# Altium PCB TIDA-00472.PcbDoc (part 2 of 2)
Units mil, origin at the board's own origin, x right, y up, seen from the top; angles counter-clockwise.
Board outline 3661.41 x 4133.85 mil, 2 copper layers (Top Layer, Bottom Layer), stack 62 mil thick; 187 components, 96 nets, 460 pads, 195 vias.
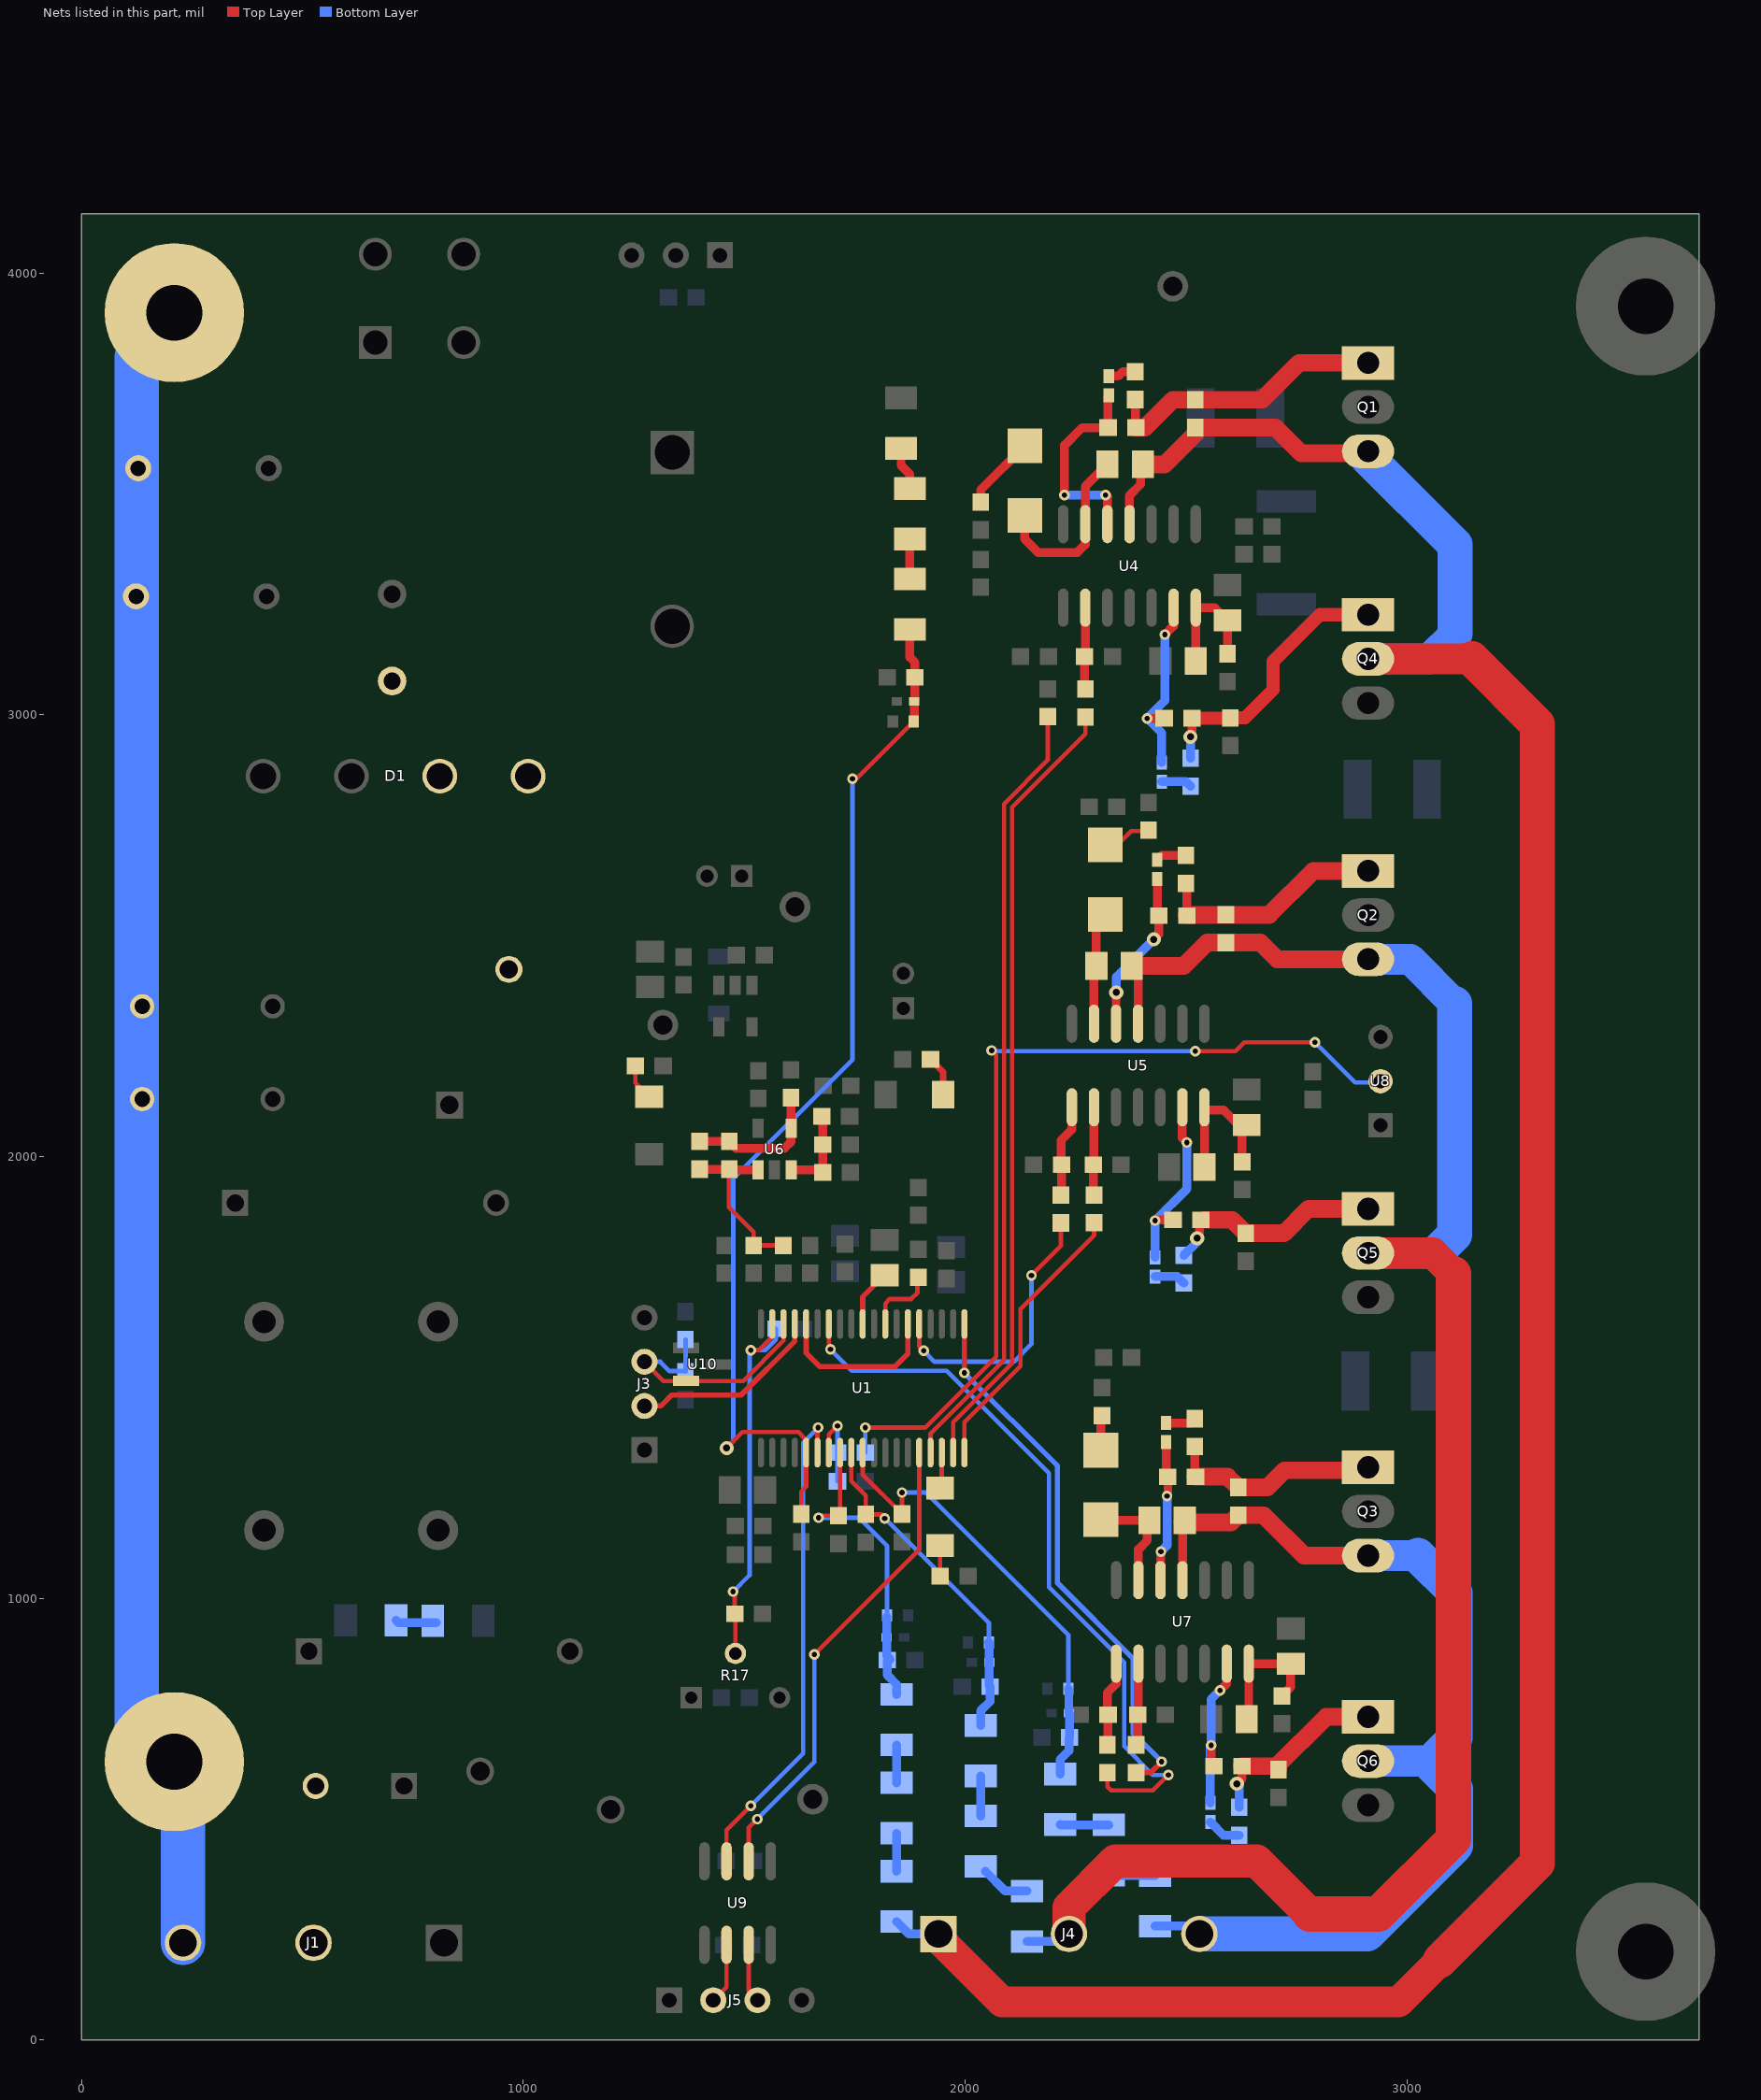
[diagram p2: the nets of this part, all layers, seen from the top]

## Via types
v1: diameter 32, hole 16, Top Layer to Bottom Layer, tented both sides, 154 vias
v2: diameter 24, hole 12, Top Layer to Bottom Layer, tented both sides, 39 vias
v3: diameter 28, hole 14, Top Layer to Bottom Layer, tented bottom, 2 vias

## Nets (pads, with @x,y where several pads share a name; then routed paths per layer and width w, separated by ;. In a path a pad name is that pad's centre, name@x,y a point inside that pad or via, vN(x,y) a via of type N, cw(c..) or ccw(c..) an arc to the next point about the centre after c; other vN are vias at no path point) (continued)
NetC28_1: C28.1 D3.1 U4.13 | length 405.7
  Top Layer w20: D3.1@2135,3451.26 2135,3397.5 2165,3367.5 2254,3367.5 2272,3385.5 U4.13@2272,3431.43 2272,3516.94 C28.1@2317,3561.94
NetC29_1: C29.1 R33.2 U4.2 | length 185.7
  Top Layer w20: R33.2@2272,3058 2270.5,3059.5 C29.1@2270.5,3131.94 2272,3133.43 U4.2@2272,3242.45
NetC30_2: C30.2 C31.1 R36.2 U4.7 | length 280
  Top Layer w20: C30.2@2522,3121.94 U4.7@2522,3242.45 2565.06,3242.45 C31.1@2594,3213.5 R36.2@2594,3138
NetC32_1: C32.1 R42.2 U5.1 | length 210.3
  Top Layer w20: R42.2@2216.57,1912.57 2218.06,1914.06 C32.1@2218.06,1981.07 2217,1982.13 2217,2036.5 2241.57,2061.07 U5.1@2241.57,2111.58
NetC34_1: C34.1 D4.1 U5.13 | length 270.8
  Top Layer w20: U5.13@2291.57,2300.56 2291.57,2415.07 C34.1@2297,2420.5 ; C34.1@2297,2431.5 D4.1@2297,2514.76 ; D4.1@2314,2531.76 D4.1@2297,2514.76 ; D4.1@2317,2547.76 2297,2527.76 D4.1@2297,2514.76
NetC35_1: C35.1 R45.2 U5.2 | length 200
  Top Layer w20: U5.2@2291.57,2111.58 2291.57,1982.57 C35.1@2290.07,1981.07 2290.07,1914.93 R45.2@2292,1913
NetC36_1: C36.1 R47.1 R52.1 R57.1 U6.1 | length 396.4
  Top Layer w10: R47.1@1466.08,1971.26 1465,1970.19 1465,1885 1521.08,1828.92 R52.1@1521.08,1798.76 R57.1@1588.28,1798.76
  Top Layer w20: C36.1@1399.08,1971.26 R47.1@1466.08,1971.26 1468.07,1969.27 U6.1@1531.27,1969.27
NetC36_2: C36.2 R47.2 R49.2 U6.4 | length 319.1
  Top Layer w20: C36.2@1399.08,2034.26 R47.2@1466.08,2034.26 1481.57,2018.76 1591.08,2018.76 1606.08,2033.76 U6.4@1606.08,2063.76 R49.2@1606.08,2133.26
NetC37_2: C37.2 C38.1 R50.2 U5.7 | length 335.2
  Top Layer w20: C37.2@2541.57,1976.07 U5.7@2541.57,2111.58 2548.15,2105 2585,2105 2618.5,2071.5 C38.1@2637,2071.5 2627,2061.5 R50.2@2627,1988
NetC40_1: C40.1 R54.2 R58.2 U6.3 | length 201.6
  Top Layer w20: U6.3@1606.08,1969.27 1672.07,1969.27 C40.1@1677.58,1963.76 R58.2@1677.58,2026.76 1677.58,2088.76 R54.2@1675.58,2090.76
NetC41_1: C41.1 R56.2 U7.1 | length 193.5
  Top Layer w20: R56.2@2322,668 2323.5,669.5 C41.1@2323.5,736.5 2322,738 2322,786.5 2342,806.5 U7.1@2342,852.02
NetC43_1: C43.1 D5.1 U7.13 | length 256.4
  Top Layer w20: D5.1@2307,1177.76 2308.26,1176.5 C43.1@2417,1176.5 2412,1171.5 2412,1130.5 2392,1110.5 U7.13@2392,1040.99
NetC44_1: C44.1 R59.2 U7.2 | length 186.1
  Top Layer w20: R59.2@2387,668 2390.5,671.5 C44.1@2390.5,736.5 2392,738 U7.2@2392,852.02
NetC45_2: C45.2 C46.1 R62.2 U7.7 | length 303.6
  Top Layer w20: C45.2@2637,726.5 2642,731.5 U7.7@2642,852.02 2736.49,852.02 C46.1@2737,851.5 2737,799 R62.2@2717,779
NetC54_1: C54.1 U1.29 | length 131.6
  Top Layer w12: U1.29@1768.08,1620.93 1768.08,1682.26 1817.08,1731.26 C54.1@1818.08,1731.26
NetD1_1: D1.1 L1.1
NetD1_2: D1.2 RT1.2
NetD2_1: D2.1 R7.2 | length 69.5
  Top Layer w10: D2.1@1943.08,1119.3 1943.08,1050.43 R7.2@1943.5,1050
NetD2_2: D2.2 U1.17 | length 106.1
  Top Layer w10: D2.2@1938.12,1227.26 1938.12,1249.22 1947.21,1258.32 U1.17@1947.21,1329.59
NetD3_2: D3.2 R31.2 | length 168.7
  Top Layer w20: R31.2@2035,3481.5 2035,3508.74 D3.2@2135,3608.74
NetD4_2: D4.2 R41.2 | length 112.2
  Top Layer w10: D4.2@2317,2705.24 2344.24,2705.24 2375.5,2736.5 2412,2736.5 R41.2@2415,2733.5
NetD5_2: D5.2 R55.2 | length 79.5
  Top Layer w20: D5.2@2307,1335.24 2307,1410.5 R55.2@2310,1413.5
NetD6_1: D6.1 R66.2 | length 91.8
  Top Layer w15: R66.2@1921.5,2220 1949.96,2191.54 D6.1@1949.96,2140
NetD7_1: D7.1 R67.2 | length 83.1
  Top Layer w10: R67.2@1253.5,2205 1253.5,2166.46 D7.1@1285,2134.96
NetD13_1: D13.1 R34.1 U4.12 | length 467.9
  Top Layer w20: v2(2225,3497.5) 2225,3610 2265,3650 R34.1@2323.5,3650 2323.5,3721.85 D13.1@2325,3723.35 ; v2(2318,3497.5) 2322,3493.5 U4.12@2322,3431.43
  Bottom Layer w20: v2(2225,3497.5) v2(2318,3497.5) v2@2322,3493.5
NetD13_2: D13.2 R2.1 | length 64.1
  Top Layer w20: D13.2@2325,3766.65 2346.65,3766.65 2356.5,3776.5 R2.1@2385,3776.5
NetD14_1: D14.1 R37.1 U4.6 | length 419.4
  Top Layer w20: v2(2411.94,2991.94) R37.1@2442,2991.94 ; v2(2452,3181.5) 2472,3201.5 U4.6@2472,3242.45
  Bottom Layer w20: D14.1@2445,2891.65 2445,2958.87 v2(2411.94,2991.94) 2452,3032 v2(2452,3181.5)
NetD14_2: D14.2 R3.1 | length 69.1
  Bottom Layer w20: D14.2@2445,2848.35 2500.16,2848.35 R3.1@2510,2838.5
NetD15_1: D15.1 R46.1 U5.12 | length 352.1
  Top Layer w20: U5.12@2341.57,2300.56 2341.57,2361.07 v1@2342,2361.5 ; v1(2427,2491.5) 2438.5,2503.01 R46.1@2438.5,2545 ; D15.1@2435,2628.35 2435,2553.01 R46.1@2436.5,2551.5
  Bottom Layer w20: v1(2342,2371.5) 2342,2406.5 v1(2427,2491.5)
NetD15_2: D15.2 R6.1 | length 69.1
  Top Layer w20: D15.2@2435,2671.65 2444.84,2681.5 R6.1@2500,2681.5
NetD16_1: D16.1 R51.1 U5.6 | length 406.7
  Top Layer w20: v2(2430,1855) 2431.5,1856.5 R51.1@2462,1856.5 ; U5.6@2491.57,2111.58 2491.57,2041.94 v2(2502,2031.5)
  Bottom Layer w20: D16.1@2430,1771.65 v2(2430,1855) 2502,1927 v2(2502,2031.5)
NetD16_2: D16.2 R24.1 | length 71.1
  Bottom Layer w20: D16.2@2430,1728.35 2480.16,1728.35 R24.1@2495,1713.5
NetD17_1: D17.1 R60.1 U7.12 | length 320.8
  Top Layer w20: U7.12@2442,1040.99 2443,1041.99 v2(2443,1105.5) ; D17.1@2455,1353.35 2455,1278.5 R60.1@2458.5,1275 ; v2(2457,1231.5) 2459,1233.5 R60.1@2459,1275
  Bottom Layer w20: v2(2443,1105.5) 2457,1119.5 v2(2457,1231.5)
NetD17_2: D17.2 R25.1 | length 69.1
  Top Layer w20: D17.2@2455,1396.65 2510.16,1396.65 R25.1@2520,1406.5
NetD18_1: D18.1 R63.1 U7.6 | length 377.7
  Top Layer w20: R63.1@2557,620 v2(2557,667) ; v2(2577,791.5) 2592,806.5 U7.6@2592,852.02
  Bottom Layer w20: D18.1@2555,536.65 2555,665 v2(2557,667) 2557,771.5 v2(2577,791.5)
NetD18_2: D18.2 R26.1 | length 77.4
  Bottom Layer w20: D18.2@2555,493.35 2584.84,463.5 R26.1@2620,463.5
NetF1_2: F1.2 J1.2
NetR1_1: R1.1 R4.2 | length 92.9
  Bottom Layer w20: R1.1@712.09,950 717.09,945 R4.2@802.91,945
NetR8_1: R8.1 R13.2 | length 99.1
  Top Layer w20: R8.1@1855,3602.91 1855,3564.49 1875,3544.49 R13.2@1875,3512.09
NetR9_1: R9.1 R14.2 | length 85.8
  Bottom Layer w20: R9.1@1845,382.09 R14.2@1845,467.91
NetR10_1: R10.1 R15.2 | length 112.8
  Bottom Layer w20: R15.2@2045.83,382.09 2090.83,337.09 R10.1@2140,337.09
NetR11_1: R11.1 R16.2 | length 105.3
  Bottom Layer w20: R16.2@2325,372.91 2325.83,372.09 R11.1@2430,372.09
NetR13_1: R13.1 R18.2 | length 90.8
  Top Layer w20: R18.2@1875,3307.09 R13.1@1875,3397.91
NetR14_1: R14.1 R19.2 | length 85.8
  Bottom Layer w20: R14.1@1845,582.09 R19.2@1845,667.91
NetR15_1: R15.1 R20.2 | length 90.8
  Bottom Layer w20: R15.1@2035,507.09 R20.2@2035,597.91
NetR16_1: R16.1 R21.2 | length 110.3
  Bottom Layer w20: R21.2@2215,487.91 2215.83,487.09 R16.1@2325,487.09
NetR65_2: R65.2 U8.2 | length 2046
  Top Layer w10: v2(1774.08,1386.26) 1909.43,1386.26 2070,1546.83 2070,2230 v2(2060,2240) ; v2(2521,2238.5) 2612,2238.5 2632,2258.5 v2(2792,2258.5)
  Bottom Layer w10: R65.2@1773.98,1329.59 1773.98,1386.17 v2(1774.08,1386.26) ; v2(2060,2240) 2061.5,2238.5 v2(2521,2238.5) ; v2(2792,2258.5) 2883,2167.5 2940,2167.5 U8.2@2940,2170.5
NetR68_2: R68.2 U1.27 | length 165.5
  Top Layer w10: U1.27@1819.26,1620.93 1819.26,1667.45 1829.08,1677.26 1878.08,1677.26 1892.08,1691.26 1892.08,1724.77 R68.2@1894.08,1726.77
OC_FLT: U1.25 U1.34 | length 388.3
  Top Layer w12: U1.34@1640.12,1620.93 1640.12,1555.22 1671.08,1524.26 1841.08,1524.26 1870.44,1553.63 U1.25@1870.44,1620.93
PE: C1.1 C5.2 C6.2 C7.1 H1.1 H3.1 J1.3 | length 3774.8
  Bottom Layer w100: H3.1@225,3910 125,3810 125,715 H1.1@210,630 229.72,610.28 J1.3@229.72,220
PHU: C28.2 J4.1 Q1.3 Q4.2 R9.2 R35.1 U4.11 | length 6108.5
  Top Layer w20: U4.11@2372,3431.43 2372,3496.5 2397,3521.5 C28.2@2397,3561.94
  Top Layer w40: C28.2@2402,3566.94 2451.94,3566.94 2521,3636 R35.1@2521,3650.01 2702.5,3650.01 2761,3591.5 2907,3591.5 Q1.3@2912,3596.5
  Top Layer w70: J4.1@1939.72,230 2083.72,86 2981,86 3075,180 ; Q4.2@2912,3126.5 3147,3126.5
  Top Layer w80: 3075,180 3295,400 3295,2978.5 3147,3126.5
  Bottom Layer w20: R9.2@1845,267.91 1872.91,240 J4.1@1939.72,240
  Bottom Layer w70: Q4.2@2912,3126.5 3051,3126.5 3109,3184.5 ; Q1.3@2912,3581.5 Q1.3@2912,3596.5
  Bottom Layer w80: Q1.3@2912,3581.5 3109,3384.5 3109,3184.5
PHU_FB: C21.1 D9.2 R19.1 R28.2 U1.8 U11.1 | length 716.2
  Top Layer w10: v2(1668.08,1182.26) 1672.57,1186.76 C21.1@1713.08,1186.76 1716.9,1190.58 U1.8@1716.9,1329.59
  Bottom Layer w10: v2(1668.08,1182.26) 1759.5,1182.26 1823.38,1118.39 D9.2@1823.38,961.5
  Bottom Layer w20: D9.2@1822.32,957.57 U11.1@1822.32,911.5 1822.32,869.69 R28.2@1830.5,861.5 ; R28.2@1823.5,860 1823.5,826.5 1845,805 R19.1@1845,782.09
PHV: C34.2 J4.2 Q2.3 Q5.2 R10.2 R48.1 U5.11 | length 4359.4
  Top Layer w20: C34.2@2377,2420.5 2391.57,2405.94 U5.11@2391.57,2300.56
  Top Layer w40: C34.2@2377,2431.5 2495,2431.5 2547.5,2484.01 R48.1@2590,2484.01 2668.5,2484.01 2706,2446.5 Q2.3@2912,2446.5
  Top Layer w70: Q5.2@2912,1781.5 3058.5,1781.5 3105,1735
  Top Layer w75: J4.2@2235,240 2235,300 2340,405 2660,405 2780,285
  Top Layer w80: 2780,285 2935,285 3105,455 3105,1735
  Bottom Layer w20: R10.2@2140,222.91 2217.91,222.91 J4.2@2235,240
  Bottom Layer w70: Q5.2@2912,1781.5 3066,1781.5 ; Q2.3@2912,2446.5 3007,2446.5 3108,2345.5
  Bottom Layer w80: 3066,1781.5 3108,1823.5 3108,2345.5
PHV_FB: C22.1 D11.2 R20.1 R29.2 U1.9 U13.1 | length 766.4
  Top Layer w10: U1.9@1742.49,1329.59 1742.49,1264.85 1775.08,1232.26 C22.1@1775.08,1189.76 1810.58,1189.76 1811.08,1189.26 v2@1812.08,1189.26
  Bottom Layer w10: v2(1818.08,1180.26) 2053.62,944.72 D11.2@2053.62,900
  Bottom Layer w20: R20.1@2035,712.09 2035,745 2056.5,766.5 R29.2@2056.5,800 2054.68,801.81 U13.1@2054.68,855 2054.68,898.94 D11.2@2053.62,900
PHW: C43.2 J4.3 Q3.3 Q6.2 R11.2 R61.1 U7.11 | length 2355.2
  Top Layer w20: U7.11@2492,1040.99 C43.2@2492,1171.5
  Top Layer w40: C43.2@2492,1171.5 2601.5,1171.5 R61.1@2618,1188.01 2675.5,1188.01 2767,1096.5 Q3.3@2912,1096.5
  Bottom Layer w20: R11.2@2430,257.91 2512.36,257.91 J4.3@2530.28,240
  Bottom Layer w70: Q6.2@2912,631.5 3056,631.5 ; Q3.3@2912,1096.5 3025,1096.5
  Bottom Layer w80: J4.3@2530.28,240 2910,240 3110,440 3110,567.5 3051,626.5 ; 3025,1096.5 3109,1012.5 3109,684.5 3056,631.5
PHW_FB: C23.1 D10.2 R21.1 R30.2 U1.10 U12.1 | length 1059.5
  Top Layer w10: U1.10@1768.08,1329.59 1768.08,1279.76 C23.1@1857.08,1190.76 v2(1857.08,1239.26)
  Bottom Layer w10: v2(1857.08,1239.26) 1911.75,1239.26 2233.62,917.39 D10.2@2233.62,795
  Bottom Layer w20: R21.1@2215,602.09 2215,635 2235,655 2235,683.5 R30.2@2236.5,685 2236.5,738.19 U12.1@2234.68,740 2234.68,793.94 D10.2@2233.62,795
PWM_U_BOT: R33.1 U1.18 | length 1789.3
  Top Layer w10: U1.18@1972.8,1329.59 1972.8,1398.72 2106,1531.92 2106,2791.05 2272,2957.05 R33.1@2272,2995.01
PWM_U_TOP: R32.1 U1.16 | length 1775.8
  Top Layer w10: U1.16@1921.62,1329.59 1921.62,1373 2088,1539.38 2088,2798.5 2187,2897.5 R32.1@2187,2995.44
PWM_V_BOT: R45.1 U1.19 | length 642
  Top Layer w10: U1.19@1998.39,1329.59 1998.39,1398.86 2125,1525.46 2125,1655 2292,1822 R45.1@2292,1850.01
PWM_V_TOP: R42.1 U1.24 | length 642.1
  Top Layer w10: U1.24@1896.03,1620.93 1896.03,1570.31 v2(1906.08,1560.26) ; v2(2150,1730.5) 2216.57,1797.07 R42.1@2216.57,1849.57 R42.1@2213.5,1846.5
  Bottom Layer w10: v2(1906.08,1560.26) 1931.08,1535.26 2110.26,1535.26 2150,1575 v2(2150,1730.5)
PWM_W_BOT: R59.1 U1.20 | length 1244.5
  Top Layer w12: v2(1998.08,1510.26) 1998.08,1620.62 U1.20@1998.39,1620.93 ; R59.1@2387,605.01 2420.01,605.01 v2(2445,630)
  Bottom Layer w12: v2(1998.08,1510.26) 2209,1299.34 2209,1034.5 2380,863.5 2380,695 v2(2445,630)
PWM_W_TOP: R56.1 U1.32 | length 1673.4
  Top Layer w10: U1.32@1691.3,1620.93 1691.3,1567.04 v2(1695.08,1563.26) ; R56.1@2322,605.01 2322,573 2330,565 2425,565 v2(2460,600)
  Bottom Layer w10: v2(1695.08,1563.26) 1743.34,1515 1957.99,1515 2190,1282.99 2190,1025 2360,855 2360,665.02 2425.02,600 v2(2460,600)
RST: C57.1 J3.3 R12.1 U1.36 U10.2 | length 583.8
  Top Layer w10: J3.3@1274.08,1535.26 1317.48,1491.86 U10.2@1368.68,1491.86 1497.68,1491.86 1588.94,1583.13 U1.36@1588.94,1620.93
  Bottom Layer w10: J3.3@1274.08,1535.26 1310.08,1535.26 1331.08,1514.26 1365.57,1514.26 R12.1@1367.08,1512.76 C57.1@1367.08,1585.77
RX_IN: J5.3 U9.7 | length 133.8
  Top Layer w10: U9.7@1510,215.51 1510,110 J5.3@1530,90
SPEED_REF: C15.1 R17.2 R22.2 U1.37 | length 886.3
  Top Layer w10: v2(1475,1015) 1478.5,1011.5 R22.2@1478.5,965 1480,963.5 R17.2@1480,875 ; v2(1515.08,1561.26) 1532.8,1561.26 1563.35,1591.82 U1.37@1563.35,1620.93
  Bottom Layer w10: v2(1475,1015) 1512.08,1052.08 1512.08,1558.26 v2(1515.08,1561.26) 1547.34,1561.26 1571.58,1585.5 C15.1@1571.58,1610.26
TEMP_SENSE: C53.1 R65.1 U1.7 | length 194.1
  Top Layer w10: U1.7@1691.3,1329.59 1691.3,1370.49 v2(1710.99,1390.18)
  Bottom Layer w10: C53.1@1710.99,1264.85 R65.1@1710.99,1329.59 v2(1710.99,1390.18)
TEST: J3.2 U1.35 | length 440.3
  Top Layer w12: J3.2@1274.08,1435.26 1310.92,1435.26 1335.66,1460 1492.81,1460 1614.53,1581.72 U1.35@1614.53,1620.93
TX_OUT: J5.2 U9.6 | length 137.9
  Top Layer w10: J5.2@1430,90 1460,120 U9.6@1460,215.51
U_BOT: Q4.1 R3.2 R37.2 R38.2 | length 616.5
  Top Layer w20: v1(2510,2950) 2513.5,2953.5 R37.2@2513.5,2991.94
  Top Layer w30: R37.2@2522,2991.94 2598.94,2991.94 R38.2@2600,2993 2633.5,2993 2697,3056.5 2697,3120.5 2803,3226.5 Q4.1@2912,3226.5
  Bottom Layer w20: R3.2@2510,2901.5 v1(2510,2950)
U_TOP: Q1.1 R2.2 R34.2 R35.2 | length 650.3
  Top Layer w20: R2.2@2385,3713.5 2385,3651.5 R34.2@2386.5,3650
  Top Layer w40: R34.2@2386.5,3650 2407,3650 2470,3713 R35.2@2521,3713 2672.5,3713 2756,3796.5 Q1.1@2912,3796.5
UART_RX: U1.15 U9.2 | length 1085
  Top Layer w10: U9.2@1510,404.49 1510,480.1 v2(1529.9,500) ; v2(1659,872.92) 1896.03,1109.95 U1.15@1896.03,1329.59
  Bottom Layer w10: v2(1529.9,500) 1659,629.1 v2(1659,872.92)
UART_TX: U1.6 U9.3 | length 1124.8
  Top Layer w10: U9.3@1460,404.49 1460,475.36 v2(1514.64,530) ; U1.6@1665.71,1329.59 1665.71,1384.9 v2(1667.08,1386.26)
  Bottom Layer w10: v2(1514.64,530) 1633.08,648.43 1633.08,1352.26 v2(1667.08,1386.26)
V_BOT: Q5.1 R24.2 R51.2 R53.2 | length 501.6
  Top Layer w20: v1(2525,1815) 2530,1820 2530,1853.01 R51.2@2533.5,1856.5
  Top Layer w40: R51.2@2542,1856.5 2604.5,1856.5 R53.2@2635,1826 2721.5,1826 2777,1881.5 Q5.1@2912,1881.5
  Bottom Layer w20: R24.2@2495,1776.5 2525,1806.5 v1(2525,1815)
V_TOP: Q2.1 R6.2 R46.2 R48.2 | length 525.8
  Top Layer w20: R6.2@2500,2618.5 2501.5,2617.01 2501.5,2547 R46.2@2501.5,2545
  Top Layer w40: R46.2@2501.5,2547 R48.2@2590,2547 2688.5,2547 2788,2646.5 Q2.1@2912,2646.5
VDC_FB: C20.1 D12.2 R18.1 R27.2 U1.5 U3.1 | length 2414.2
  Top Layer w10: v1(1460,1340) 1496.06,1376.06 1622.77,1376.06 1640.12,1358.71 U1.5@1640.12,1329.59 1640.12,1252.31 1629.08,1241.26 C20.1@1629.08,1190.76 ; v2(1745,2855) 1753.62,2855 D12.2@1883.62,2985
  Top Layer w20: R18.1@1875,3192.91 1875,3130 1886.5,3118.5 R27.2@1886.5,3085 1886.5,3031.81 U3.1@1884.68,3030 1884.68,2986.06 D12.2@1883.62,2985
  Bottom Layer w10: v1(1460,1340) 1475.08,1355.08 1475.08,1949.72 1745,2219.64 v2(1745,2855)
W_BOT: Q6.1 R26.2 R63.2 R64.2 | length 442
  Top Layer w20: v1(2615,580) 2626.5,591.5 R63.2@2626.5,620
  Top Layer w40: R63.2@2626.5,620 2701,620 R64.2@2703.25,617.75 ; R64.2@2709,612 R64.2@2703.25,617.75 ; Q6.1@2912,731.5 2817,731.5 R64.2@2703.25,617.75
  Bottom Layer w20: v1(2615,580) 2620,575 R26.2@2620,526.5
W_TOP: Q3.1 R25.2 R60.2 R61.2 | length 488.4
  Top Layer w20: R25.2@2520,1343.5 2520,1276.5 R60.2@2521.5,1275
  Top Layer w40: R60.2@2521.5,1275 2594,1275 R61.2@2618,1251 2684.5,1251 2723,1289.5 2905,1289.5 Q3.1@2912,1296.5
pads on no net: H2.1 H4.1 U1.2 U1.3 U1.11 U1.12 U1.13 U1.14 U1.23 U1.26 U1.28 U4.8 U4.9 U4.10 U4.14 U5.8 U5.9 U5.10 U5.14 U7.8 U7.9 U7.10 U7.14

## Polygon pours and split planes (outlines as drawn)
NetC4_2 on Top Layer "Top Layer-No Net" (solid, pour order 29): 780,175 775,175 760,190 760,310 780,330 990,330 1164,504 1166,506 1166,556 1102,620 1102,830 1085,847 837,1095 809,1095 775,1095 750,1120 750,1190 765,1205 834,1205 845,1194 1183,856 1183,771 1183,627 1234,576 1234,457 952,175 865,175
+VDC on Top Layer "Top Layer-No Net" (solid, pour order 26): 640.5,4075.5 625,4060 625,3653 647,3631 1281,3631 1285,3627 1285,3616 437,3616 395,3574 395,3540 406,3529 500,3529 555,3474 1421,3474 1437,3490 1437,3651 1410,3678 717,3678 704,3691 704,4061 689.5,4075.5
AGND on Top Layer "Top Layer-VCC_15V" (solid, remove dead copper, pour order 44): 1615,3175 1615,2905 1549,2905 1166,2522 1166,1151 1355,962 1355,395 1365,385 2535,385 2585,435 2540,480 2540,3465 2450,3555 2208,3555 1828,3175
NetF1_2 on Top Layer "Top Layer-VCC_15V" (solid, remove dead copper, pour order 24): 570,610 580,600 580,445 610,415 610,200 580,170 490,170 480,180 480,410 500,430 500,600 510,610
NetC4_1 on Top Layer "Top Layer-VCC_15V" (solid, remove dead copper, pour order 34): 700,550 715,535 900,535 945,580 945,750 915,780 600,780 545,835 545,1185 520,1210 375,1210 365,1200 365,1110 380,1095 460,1095 465,1093.75 465,795 600,660 875,660 880,655 880,640 870,630 710,630 700,620
NetD1_1 on Top Layer "Top Layer-VCC_15V" (solid, remove dead copper, pour order 38): 970,2801 980,2791 1045,2791 1055,2801 1055,2996 940,3111 685,3111 665,3091 665,3056 680,3041 875,3041 970,2946
+VDC on Top Layer "Top Layer-VCC_15V" (solid, remove dead copper, pour order 41): 1300,3600 1300,3480 1305,3475 1480,3475 1915,3910 2715,3910 2725,3920 2725,3995 2700,4020 1825,4020 1485,3680 1380,3680
AGND on Top Layer "Top Layer-VCC_15V" (solid, remove dead copper, pour order 45): 2845,2880 2585,2880 2570,2865 2570,2770 2580,2760 2839.16,2760 2860,2780.84 2860,2815 2860,2865 2845,2880
AGND on Top Layer "Top Layer-VCC_15V" (solid, remove dead copper, pour order 46): 2665,1445 2825,1445 2840,1460 2840,1575 2830,1585 2705,1585 2655,1635 2575,1635 2570,1630 2570,1540
NetC1_2 on Top Layer "Top Layer-VCC_15V" (solid, remove dead copper, pour order 30): 340,1575 470,1575 485,1590 485,2055 505,2075 855,2075 865,2085 865,2210 850,2225 380,2225 319,2164 319,1596
NetD1_2 on Top Layer "Top Layer-VCC_15V" (solid, remove dead copper, pour order 36): 781,2901 831,2901 850,2882 850,2500 875,2475 995,2475 1000,2470 1000,2405 985,2390 820,2390 765,2445 765,2885
NetC4_2 on Bottom Layer "Top Layer-No Net" (solid, pour order 27): 780,175 775,175 760,190 760,310 780,330 990,330 1164,504 1166,506 1166,556 1102,620 1102,830 1085,847 837,1095 809,1095 775,1095 750,1120 750,1190 765,1205 834,1205 845,1194 1183,856 1183,771 1183,627 1234,576 1234,457 952,175 865,175
NetD1_2 on Bottom Layer "Top Layer-VCC_15V" (solid, remove dead copper, pour order 35): 782,2900 832,2900 851,2881 851,2499 876,2474 996,2474 1001,2469 1001,2404 986,2389 821,2389 764,2446 764,2882
NetC4_1 on Bottom Layer "Top Layer-VCC_15V" (solid, remove dead copper, pour order 33): 700,550 715,535 900,535 945,580 945,750 915,780 600,780 545,835 545,1185 520,1210 375,1210 365,1200 365,1110 380,1095 460,1095 465,1093.75 465,795 600,660 875,660 880,655 880,640 870,630 710,630 700,620
NetD1_1 on Bottom Layer "Top Layer-VCC_15V" (solid, remove dead copper, pour order 37): 969.5,2801 979.5,2791 1044.5,2791 1054.5,2801 1054.5,2996 939.5,3111 684.5,3111 664.5,3091 664.5,3056 679.5,3041 874.5,3041 969.5,2946
AGND on Bottom Layer "Top Layer-VCC_15V" (solid, remove dead copper, pour order 42): 1305,3165 1305,3075 1320,3060 1665,3060 2225,3620 2560,3620 2570,3630 2570,3735 2555,3750 2120,3750 1540,3170 1310,3170
AGND on Bottom Layer "Top Layer-VCC_15V" (solid, remove dead copper, pour order 43): 1310,3170 1310,3070 1320,3060 1440,3060 1455,3045 1455,2811 1166,2522 1166,1151 1355,962 1355,395 1365,385 2535,385 2585,435 2540,480 2540,3465 2450,3555 2195,3555 1868,3228 1368,3228
EMT_U on Bottom Layer "Top Layer-VCC_15V" (solid, remove dead copper, pour order 25): 2657,3281.5 2792,3281.5 2797,3276.5 2797,3231.5 2792,3226.5 2752,3226.5 2747,3217.5 2747,3069 2755.33,3064 2939,3064 2966,3037 2966,3015 2940,2989 2783.43,2989 2777,2981.5 2742,2946.5 2742,1746.5 2772,1716.5 2947,1716.5 2962,1701.5 2962,1661.5 2947,1646.5 2777,1646.5 2737,1606.5 2737,626.5 2797,566.5 2947,566.5 2962,551.5 2962,511.5 2947,496.5 2747,496.5 2637,606.5 2637,1611.5 2687,1661.5 2687,1691.5 2642,1736.5 2642,2931.5 2702,2991.5 2702,3006.5 2647,3061.5 2647,3271.5
AGND on Bottom Layer "Top Layer-VCC_15V" (solid, remove dead copper, pour order 28): 2836.74,2901.5 2922,2901.5 2922,2761.76 2829.99,2761.76 2818.5,2773.26 2818.5,2883.26
AGND on Bottom Layer "Top Layer-VCC_15V" (solid, remove dead copper, pour order 32): 2917,1562 2917,1426.5 2797,1426.5 2787,1436.5 2787,1562
+VDC on Bottom Layer "Top Layer-VCC_15V" (solid, remove dead copper, pour order 31): 2640,3995 2640,3940 2640,3916 2655,3901 2655,3605 2710,3605 2715,3610 2715,3659 3065.89,3659 3255,3475 3255,3055 3101,2901 3012,2901 3012,2765 3080,2765 3200,2645 3200,2590 3190,2580 2874,2580 2874,2513.06 3035,2513 3196,2513 3197.94,2512.06 3250,2460 3250,1720 3091,1561 3007,1561 3007,1425 3145,1425 3235,1335 3235,1285 3182,1232 2880,1232 2880,1165 3255,1165 3350,1260 3350,1355 3230,1475 3230,1555 3360,1685 3360,2610 3165,2805 3165,2835 3355,3025 3355,3515 3135,3735 2735,3735 2728,3742 2728,3992 2710,4010 2655,4010
AGND on Bottom Layer "Top Layer-VCC_15V" (solid, remove dead copper, pour order 39): 368,2813 456,2813 460,2817 460,3257 639,3436 816,3436 1192,3060 1400,3060 1415,3075 1415,3145 1350,3210 1244,3210 916,3538 623,3538 360,3275 360,2821
AGND on Bottom Layer "Top Layer-VCC_15V" (solid, remove dead copper, pour order 40): 1285,3191 830,3646 830,4070 840,4080 890,4080 900,4070 900,3708 1415,3193 1415,3075 1400,3060 1300,3060 1285,3075

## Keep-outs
Keep-Out Layer:
  lines w6: 40,4093.85 40,40 55,40 3700.15,40 3700.15,4093.85 55,4093.85
  text ".Layer_Name" at -83,-1959.49 h60

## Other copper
Top Layer:
  pour cut-out: 1965,3340 1999,3306 1999,3054.32 1998.68,3054 1930.65,3054 1831,3175 1831,3329 1842,3340
  pour cut-out: 1620,370 1710,460 1710,620 1725,635 2265,635 2275,625 2300,625 2390,535 2445,535 2535,445 2760,445 2835,370 2835,75 2810,50 1305,50 1290,65 1290,365 1295,370
  text ".layer_Name" at -68,-1949 h60
Bottom Layer:
  pour cut-out: 1615,370 1705,460 1705,815 1715,825 1855,825 1930,750 2075,750 2095,730 2095,645 2105,635 2260,635 2270,625 2295,625 2385,535 2440,535 2530,445 2755,445 2830,370 2830,75 2805,50 1300,50 1285,65 1285,365 1290,370
  text ".Layer_Name" at -9,-1959 h60
Multi-Layer:
  pour cut-out: 2197,2180 2197,2713.5 2515.5,2713.5 2547,2682 2547,2180
  pour cut-out: 2168,1407.5 2621,1407.5 2627,1401.5 2627,925.5 2304.15,925.5 2168,1062.86
  pour cut-out: 2050,3284.5 2050,3425 2160.5,3535.5 2527.5,3535.5 2554.5,3508.5 2554.5,3301.5 2537.5,3284.5

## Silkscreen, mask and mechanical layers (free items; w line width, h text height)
Top Overlay:
  circle w6: c1547.8,2383.98 r5.83
  circle w6: c775.78,2115 r9.22
  circle w6: c1524.61,1935 r5.39
  circle w6: c1369.08,1598.26 r5.39
  circle w6: c1509.9,1355 r5.1
  circle w6: c2309,861.5 r7.62
  circle w6: c2211,2120.5 r5.39
  circle w6: c2196,3248.5 r7.07
  circle w6: c1170,1120 r10
  circle w6: c1590,400 r7.07
  lines w6: 1497,2083 1500,2083 1509,2074 1509,2070 ; 1640,1935 1640,2075 ; 1645,2195 1645,2205 1685,2205 ; 1735,2205 1775,2205 1780,2200 1780,1930 1775,1925 1750.31,1925 1750.08,1925.24 ; 1745,2431.96 1736.96,2440 1655,2440 1640,2425 1640,2290 1640,2280 1655,2265 1735,2265 1750,2280 1750,2315 ; 1755,2205 1755,2255 ; 1825,3020 1825,3045 ; 1905,3020 1905,3045 ; 1911.08,1696.26 1911.08,1684.26 1927.08,1668.26 2010.08,1668.26 2018.08,1668.26 ; 2355.57,1953.87 2355.57,1944.94 2364,1936.5 2364,1930.5 ; 2575,2605 2545,2605 ; 1755,2255 1745,2245 1765,2245 1755,2255 ; 2545,2605 2555,2615 2555,2595 2545,2605
  text "+5V" at 1362,3894 h30 r90
  text "GND" at 1464,3893 h30 r90
  text "+15V" at 1263,3870 h30 r90
  text "TIDA-00472-E2" at 1660,3790 h100
  text "GND" at 887,3638 h30 r90
  text "VDC_BUS" at 680,3480 h30 r90
  text "A" at 1235,2126 h30 r90
  text "A" at 1941,2060 h30
  text "GND" at 1234,1698 h30
  text "RST" at 1211,1509 h30 r90
  text "TEST" at 1212,1350 h30 r90
  text "+3.3V" at 1205,1240 h30
  text "A" at 2020,1106 h30 r90
  text "MU" at 1915,439 h40
  text "MV" at 2213,436 h40
  text "MW" at 2498,428 h40
  text "L" at 485,415 h40
  text "PE" at 221,414 h40
  text "N" at 867,410 h40
  text "ISO_VCC" at 1719,62 h25 r90
  text "ISO_GND" at 1260,60 h25 r90
  text "TX_OUT" at 1347,7 h25
  text "RX_IN" at 1532,6 h25
  text ".layer_Name" at -42,-1947 h60
Bottom Overlay:
  lines w6: 1802,898 1802,926 ; 1882,897 1882,925 ; 1994,838 1994,866 ; 2078,840 2078,868 ; 2175,725 2175,753 ; 2258,726 2258,754
  text ".Layer_Name" at -83,-1959.49 h60
Top Paste:
  text ".Layer_Name" at -95,-1962.49 h60
Bottom Paste:
  text ".Layer_Name" at -95,-1962.49 h60
Top Solder:
  text ".Layer_Name" at -67,-1970 h60
Bottom Solder:
  text ".Layer_Name" at -20,-1966 h60
M1 Board Outline:
  lines w6: 0,0 0,4133.85 3740.15,4133.85 3740.15,0 0,0
  text "M1 Board outline" at -42,-1946 h30
M2 Board Dimensions:
  rectangle: -190.5,-981 -65.5,-856
  rectangle: -65.5,-1106 309.5,-981
  lines w7: -190.5,-981 809.5,-981 ; -65.5,-1106 -65.5,-856 ; 59.5,-1106 59.5,-856 ; 309.5,-1106 309.5,-856 ; 559.5,-1106 559.5,-856 ; -190.5,-1106 809.5,-1106 809.5,-856 -190.5,-856 -190.5,-1106
  lines w10: -190.5,-1171 -190.5,-1151 ; -130.5,-1181 -190.5,-1161 ; -130.5,-1141 -190.5,-1161 ; 33.58,-1161 -190.5,-1161 ; 585.42,-1161 809.5,-1161 ; 749.5,-1181 809.5,-1161 ; 749.5,-1141 809.5,-1161 ; 809.5,-1171 809.5,-1151
  text "1000 (mil)" at 43.58,-1196.99 h60
M3 3D STEP Top:
  text ".Layer_Name" at -83,-1959.49 h60
M4 3D STEP Bottom:
  text ".Layer_Name" at -83,-1959.49 h60
M5 Assembly Top:
  circle w6: c1545.68,2387 r6.32
  circle w6: c1368.39,1598 r3.61
  circle w6: c1275.75,1336 r8.25
  circle w6: c1255.72,83 r7.28
  circle w6: c2966.68,2057 r6.32
  circle w6: c771,2116 r9
  circle w6: c1009.88,1063 r16.12
  circle w6: c1453,3976 r7.07
  circle w6: c1530.68,1944 r6.32
  circle w6: c2470,3970 r36.72
  circle w6: c1615,2565 r36.72
  circle w6: c1315.8,2297.49 r36.72
  circle w6: c1655,545 r36.72
  lines w6: 2455,2706 2455,2711 2467,2723 2467,2726
  lines w10: -952,-2031.17 5648,-2031.17 ; -952,-1827.83 5650,-1827.83 ; -952,-1624.5 -952,-2234.5 3053,-2234.5 5650,-2234.5 5650,-1624.5 -951.5,-1624.5 -951.5,-2234.5 ; 1513,-2234.5 1513,-1624.5 ; 2780,-1827.83 2780,-1624.5 ; 3620,-1827.83 3620,-1624.5 ; 4242,-2241 4242,-2038.17
  text "TP1" at 2445,3895 h30
  text "TP2" at 1665,2550 h30
  text "TP3" at 1185,2285 h30
  text "A" at 1237,2127 h30 r90
  text "A" at 1940,2057 h30
  text "A" at 2020,1107 h30 r90
  text "TP4" at 1619,595 h30
  text "COMPONENTS MARKED 'DNP' SHOULD NOT BE POPULATED." at 493.5,-1419.5 h30
  text "ASSEMBLY VARIANT:" at 493,-1535 h30
  text ".VariantName" at 1529,-1535 h30
  text "ALL ARTWORK VIEWED FROM TOP SIDE" at -888.5,-1756.67 h30
  text "BOARD #:" at 1588,-1756.67 h30
  text ".PRJ_Number" at 2133.5,-1756.67 h30
  text "REV:" at 2978,-1756.67 h30
  text "E2" at 3269.5,-1756.67 h30
  text "SVN REV:" at 3816,-1756.67 h30
  text ".VersionControl_RevNumber" at 4322,-1756.67 h30
  text ".layer_Name" at -125,-1939 h30
  text "LAYER NAME =" at -895,-1946 h30
  text ".plot_File_Name" at -897,-2135 h30
  text "GENERATED    :" at 1590,-2165.34 h30
  text ".Print_Date" at 2459.5,-2165.34 h30
  text ".Print_Time" at 3188.5,-2165.34 h30
  text "TEXAS INSTRUMENTS" at 4453,-2165.34 h30
M6 Assembly Bottom:
  lines w6: -952.5,-1828.33 5649.5,-1828.33 ; -950.5,-2031.67 5649.5,-2031.67 ; 1077.5,-1828.33 1077.5,-1625 ; 1917.5,-1828.33 1917.5,-1625 ; 3184.5,-2235 3184.5,-1625 ; 4073.5,-2235 5649,-2235 5649,-1625 -952.5,-1625 -952.5,-2235 1644.5,-2235 5649.5,-2235 5649.5,-1625
  text "COMPONENTS MARKED 'DNP' SHOULD NOT BE POPULATED." at 5442,-1419 h30
  text ".VariantName" at 4398,-1535 h30
  text "ASSEMBLY VARIANT:" at 5437,-1535 h30
  text "SVN REV:" at 881.5,-1757.17 h30
  text "E2" at 1428,-1757.17 h30
  text "REV:" at 1719.5,-1757.17 h30
  text ".PRJ_Number" at 2564,-1757.17 h30
  text "BOARD #:" at 3109.5,-1757.17 h30
  text "PCB VIEWED FROM BOTTOM SIDE" at 5586,-1757.17 h30
  text "LAYER NAME =" at 5581,-1942 h30
  text ".Layer_Name" at 4808,-1949 h30
  text "IGNORE ->" at 1887.85,-1959.49 h30
  text ".Print_Time" at 1509,-2165.84 h30
  text ".Print_Date" at 2238,-2165.84 h30
  text "GENERATED    :" at 3107.5,-2165.84 h30
  text ".plot_File_Name" at 4780.5,-2165.84 h30
  text "PLOT NAME =" at 5586,-2165.84 h30
M9 Title Sheet:
  drawing of 57 lines, arcs and shapes, not listed
  text "1" at 79.84,6935.5 h70
  text "2" at 2575.5,6935.5 h70
  text "3" at 5064.84,6935.5 h70
  text "4" at 7571.51,6935.5 h70
  text "5" at 10070.5,6935.5 h70
  text "6" at 12575.5,6935.5 h70
  text "A" at -1076.5,5792.5 h70
  text "A" at 13723.5,5792.5 h70
  text "B" at -1076.5,3412.5 h70
  text "B" at 13723.5,3412.5 h70
  text "C" at -1076.5,1037.5 h70
  text "C" at 13723.5,1037.5 h70
  text "PROJECT TITLE:" at 10683.5,-823.5 h45
  text ".PRJ_Title" at 10660,-950 h70
  text "DESIGNED FOR:" at 10683.5,-1124.5 h45
  text ".PRJ_Customer" at 10733.5,-1264.5 h70
  text "D" at -1076.5,-1332.5 h70
  text "D" at 13723.5,-1332.5 h70
  text "FILE NAME:" at 10683.5,-1424.5 h45
  text ".PCB_File_Name_No_Path" at 10733.5,-1544.5 h70
  text "Texas Instruments (TI) and/or its licensors do not warrant the accuracy or completeness of this specification" at 5714,-1706.34 h45
  text "ENGINEER:" at 10683.5,-1714.5 h45
  text "LAYOUT BY:" at 12188.5,-1714.5 h45
  text "or any information contained therein. TI and/or its licensors do not warrant that this design will meet" at 5669.01,-1819 h45
  text ".PRJ_Engineer" at 10733.5,-1869.49 h70
  text ".PCB_Layout" at 12239,-1869.49 h70
  text "the specifications, will be suitable for your application or fit for any particular purpose, or will operate in" at 5669.01,-1931.67 h45
  text "ALTIUM DESIGNER VERSION:" at 12188.5,-2024.5 h45
  text "an implementation. TI and/or its licensors do not warrant that the design is production worthy. You should" at 5669.01,-2044.33 h45
  text "completely validate and test your design implementation to confirm the system functionality for your application." at 5714,-2157 h45
  text ".print_Scale" at 10733.5,-2157.83 h70
  text ".Application_BuildNumber" at 12239,-2157.83 h70
  text "2" at 2575.5,-2364.5 h70
  text "3" at 5064.84,-2364.5 h70
  text "4" at 7571.51,-2364.5 h70
  text "5" at 10070.5,-2364.5 h70
  text "6" at 12575.5,-2364.5 h70
M10 Fab Notes:
  drawing of 228 lines, arcs and shapes, not listed
  text "DESIGN INFORMATION" at 11721.02,5709 h60
  text "(REFER ALSO ARRAY/PANEL PROFILING INFORMATION)" at 11359.46,5547.29 h60
  text "BOARD SIZE" at 10673.46,5543 h60
  text "3740.15" at 11135.78,5415.18 h60
  text "X" at 11641.46,5415.18 h60
  text "4133.85" at 11872.78,5415.18 h60
  text "Number of Layers :" at 11076.46,5218 h60
  text "2" at 12171.27,5208 h60
  text "MIN. TRACK WIDTH:" at 11076.46,5079 h60
  text "10" at 12172.7,5079 h60
  text "MIL" at 12327.46,5079 h60
  text "MIN. CLEARANCE:" at 11076.46,4947 h60
  text "MIL" at 12327.46,4947 h60
  text "8" at 12133,4944 h60
  text "12" at 12155,4820 h60
  text "MIN. VIA DRILL SIZE:" at 11076.46,4815 h60
  text "MIL" at 12327.46,4815 h60
  text "6 MIL" at 11771.46,4673.29 h60
  text "MINIMUM ANNULAR RING" at 10747.23,4669 h60
  text "EXTERNAL" at 12479.46,4669 h60
  text "PER" at 10947.23,4551 h60
  text "IPC-D-275 CLASS 2 LEVEL C" at 11167.23,4551 h60
  text "NOTE :" at 5943.23,4460 h60
  text "MIL, HOLES" at 12655.46,4438.71 h60
  text "+/-" at 12263,4438 h60
  text "+/-" at 13117,4438 h60
  text "REGISTRATION TOLERANCES:" at 10747.23,4433 h60
  text "METAL" at 11947,4433 h60
  text "5" at 12523.2,4433 h60
  text "3" at 13356.2,4433 h60
  text "MIL" at 13472.46,4433 h60
  text "1. Only 14mil Vias are tented  on bottom side, all other are tented on both side." at 6220,4297 h60
  text "MATERIAL:" at 10672.46,4223.54 h60
  text "FR-4 High Tg" at 11658.9,4083.21 h60
  text "X" at 10939,4078 h60
  text "FR-408" at 11093.46,4074.64 h60
  text "OTHER" at 12581.46,4074.64 h60
  text "63 MIL (1.6mm) +/-10%" at 11413.56,3911.92 h60
  text "THICKNESS:" at 10747.23,3907.64 h60
  text "X" at 11285.4,3907.64 h60
  text "OTHER" at 12698.46,3907.64 h60
  text "TOLERANCE:" at 10747.23,3749.64 h60
  text "X" at 11586.53,3749.64 h60
  text "ANSI IPC-6012 TYPE 3 CLASS 2" at 11773.48,3749.64 h60
  text "OTHER +/-" at 11773.46,3593.64 h60
  text "BOW & TWIST:" at 10747.23,3436.64 h60
  text "X" at 11586.53,3436.64 h60
  text "ANSI IPC-6012 TYPE 3 CLASS 2" at 11773.48,3436.64 h60
  text "OTHER +/-" at 11773.46,3278.13 h60
  text "COPPER THICKNESS (FINISHED):" at 10672.46,3142.64 h60
  text "1.4MIL (1oz)" at 11552.46,2989.92 h60
  text "2MIL (1.4oz)" at 12319.46,2989.92 h60
  text "2.8MIL (2oz)" at 13046.46,2989.92 h60
  text "OUTER:" at 11029.46,2985.64 h60
  text "X" at 11424,2985 h60
  text "1.4MIL (1oz)" at 11552.46,2832.92 h60
  text "2.8MIL (2oz)" at 12319.46,2832.92 h60
  text "N/A" at 13046,2833.29 h60
  text "INNER SIGNAL:" at 10740.38,2828.64 h60
  text "DRILLING:" at 10672.46,2689.64 h60
  text "REFERENCE:" at 10747.23,2572.64 h60
  text "X" at 11395.46,2572.64 h60
  text "AS SHOWN" at 11582.46,2572.64 h60
  text "X" at 12296.46,2572.64 h60
  text "NC_DRILL FILES" at 12433.46,2572.64 h60
  text "PTH MIN COPPER THICKNESS:" at 10747.23,2414.64 h60
  text "X" at 12097.46,2414.64 h60
  text "1MIL" at 12234.46,2414.64 h60
  text "OTHER" at 12731.46,2414.64 h60
  text "BOARD FINISH:" at 10672.46,2255.64 h60
  text "SILKSCREEN:" at 10827.68,2137.64 h60
  text "X" at 11776.46,2137.64 h60
  text "TOP" at 11902.46,2137.64 h60
  text "X" at 12286.46,2137.64 h60
  text "BOTTOM" at 12413.46,2137.64 h60
  text "SILKSCREEN COLOR:" at 10827.68,1970.64 h60
  text "X" at 11775.42,1970.64 h60
  text "WHITE" at 11902.46,1970.64 h60
  text "OTHER" at 12413.46,1970.64 h60
  text "SOLDER RESIST COLOR:" at 10827.68,1800.64 h60
  text "X" at 11395.42,1641.44 h60
  text "GREEN" at 11522.46,1641.44 h60
  text "BLUE" at 12113.46,1641.44 h60
  text "OTHER" at 12651.46,1641.44 h60
  text "IMMERSION GOLD (ENIG)" at 11733.46,1452.92 h60
  text "ENEPIG" at 13071,1449.64 h60
  text "SURFACE FINISH:" at 10672.46,1448.64 h60
  text "X" at 11546.51,1448.64 h60
  text "IMM. TIN/SILVER OR EQUIV" at 11002,1291.64 h60
  text "OTHER" at 12433.46,1291.64 h60
  text "ARRAY/PANEL:" at 10672.46,1112.64 h60
  text "CUT AND TRIM PER MECH LAYER 1" at 11733.46,1108.35 h60
  text "N.C. ROUTE" at 11733.46,956.64 h60
  text "X" at 12412.46,956.64 h60
  text "V. SCORE" at 12599.46,956.64 h60
  text "CERTIFICATION:" at 10672.46,819.64 h60
  text "MATERIALS AND WORKMANSHIP FOR ALL PCBS" at 11397.46,819.64 h60
  text "TO MEET OR EXCEED THE REQUIREMENTS OF:" at 11397.46,721.64 h60
  text "X" at 11023.96,585.13 h60
  text "ANSI IPC-A-600F CLASS ->" at 11162.96,585.13 h60
  text "X" at 12802.02,585.13 h60
  text "2" at 12920.96,585.14 h60
  text "1" at 12605.96,583.64 h60
  text "3" at 13274.96,583.64 h60
  text "X" at 11026.02,425.64 h60
  text "UL 94V-0" at 11162.96,425.64 h60
  text "X" at 11838.02,425.64 h60
  text "RoHS" at 11974.96,425.64 h60
  text "OTHER" at 12619.36,425.64 h60
  text "PER ORDER" at 13016.42,425.64 h60
  text "VIA TENTING:" at 11890,292 h60
  text "X" at 12650,290 h60
  text "ADDITIONAL REQUIREMENTS:" at 10672.46,284.64 h60
  text "YES" at 12439.67,282.92 h60
  text "NO" at 12804.47,277.69 h60
  text "MICROSECTION:" at 10747.23,169.64 h60
  text "YES" at 11652.96,169.64 h60
  text "IMPEDANCE CONTROL:" at 11912,163 h60
  text "YES" at 12896,162 h60
  text "X" at 13438,155 h60
  text "NO" at 13271.47,144.69 h60
  text "REQUIRED" at 12514.46,13.49 h60
  text "BARE BOARD ELEC. TEST:" at 10747.23,10.64 h60
  text "NONE" at 12052.96,10.64 h60
  text "X" at 12387.46,10.64 h60
  text "PER ORDER" at 13106.46,10.64 h60
  text "MANUFACTURER'S UL:" at 10747.23,-146.36 h60
  text "RAIL" at 11912.96,-150.65 h60
  text "METAL" at 12404.77,-150.65 h60
  text "X" at 12780,-151 h60
  text "SILK" at 12916.46,-150.65 h60
M11 Gerber Information:
  lines w10: -952,-2031.17 5648,-2031.17 ; -952,-1827.83 5650,-1827.83 ; -952,-1624.5 -952,-2234.5 3053,-2234.5 5650,-2234.5 5650,-1624.5 -951.5,-1624.5 -951.5,-2234.5 ; 1513,-2234.5 1513,-1624.5 ; 2780,-1827.83 2780,-1624.5 ; 3620,-1827.83 3620,-1624.5 ; 4242,-2241 4242,-2038.17
  text "BOARD #:" at 1588,-1756.67 h60
  text ".PRJ_Number" at 2133.5,-1756.67 h60
  text "REV:" at 2978,-1756.67 h60
  text "E2" at 3269.5,-1756.67 h60
  text "SVN REV:" at 3816,-1756.67 h60
  text ".VersionControl_RevNumber" at 4322,-1756.67 h60
  text "ALL ARTWORK VIEWED FROM TOP SIDE" at -889.5,-1762.67 h60
  text "LAYER NAME =" at -891,-1946 h60
  text ".plot_File_Name" at -899,-2145 h60
  text "GENERATED    :" at 1590,-2165.34 h60
  text ".Print_Date" at 2459.5,-2165.34 h60
  text ".Print_Time" at 3188.5,-2165.34 h60
  text "TEXAS INSTRUMENTS" at 4453,-2165.34 h60
M12 Stackup:
  lines w6: 10700,6359 13250,6359 ; 10700,6463.4 13250,6463.4 ; 10640,5874 ccw(c10674,5874) 10674,5840 13276,5840 ccw(c13276,5874) 13310,5874 13310,6580 ccw(c13276,6580) 13276,6614 10674,6614 ccw(c10674,6580) 10640,6580 10640,5874
  text "Layer Stack Up Detail for: TIDA-00472_E2" at 10700,6496.1 h57
  text "Layer" at 10700,6424.4 h24
  text "Gerber" at 11595.81,6424.4 h24
  text "Copper" at 12159.33,6424.4 h24
  text "Dielectric" at 12762.04,6424.4 h24
  text "Name" at 10700,6376.4 h24
  text "Document" at 11595.81,6376.4 h24
  text "Thickness" at 12159.33,6376.4 h24
  text "Material" at 12762.04,6376.4 h24
  text "Top Solder Mask" at 10700,6283.44 h34
  text "(.GTS)" at 11595.81,6283.44 h34
  text "Solder Resist" at 12762.04,6283.44 h34
  text "Top Layer" at 10700,6186.69 h34
  text "(.GTL)" at 11595.81,6186.69 h34
  text "1.4mil" at 12159.33,6186.69 h34
  text "FR408" at 12791,6186 h34
  text "FR408" at 12793,5967 h34
  text "Bottom Layer" at 10706,5957 h34
  text "(.GBL)" at 11604,5956 h34
  text "1.4mil" at 12164,5950 h34
  text "Solder Resist" at 12756,5883 h34
  text "(.GBS)" at 11601,5876 h34
  text "Bottom Solder Mask" at 10703,5871 h34
M13 Component Bodies Top:
  text ".Layer_Name" at -83,-1959.49 h60
M14 Component Bodies Bottom:
  text ".Layer_Name" at -83,-1959.49 h60
M15 Courtyards Top:
  text ".Layer_Name" at -83,-1959.49 h60
M16 Courtyards Bottom:
  text ".Layer_Name" at -83,-1959.49 h60
Drill Drawing:
  text ".legend" at 4822,1174 h60
  text "Drill Table" at 4819,1003 h60
  text "FOR 12MIL DRILL +0/-12MIL" at 4847,797 h60
  text "FOR 14MIL DRILL +0/-14MIL" at 4845,693 h60
  text "FOR 16MIL DRILL +0/-16MIL" at 4846,589 h60
  text "FOR PTH DRILL +/-3MIL" at 4846,471 h60
  text ".layer_Name" at 22,-1943 h60

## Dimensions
0,4133.85 to 0,0 on M2 Board Dimensions
0,0 to 3740.15,0 on M2 Board Dimensions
